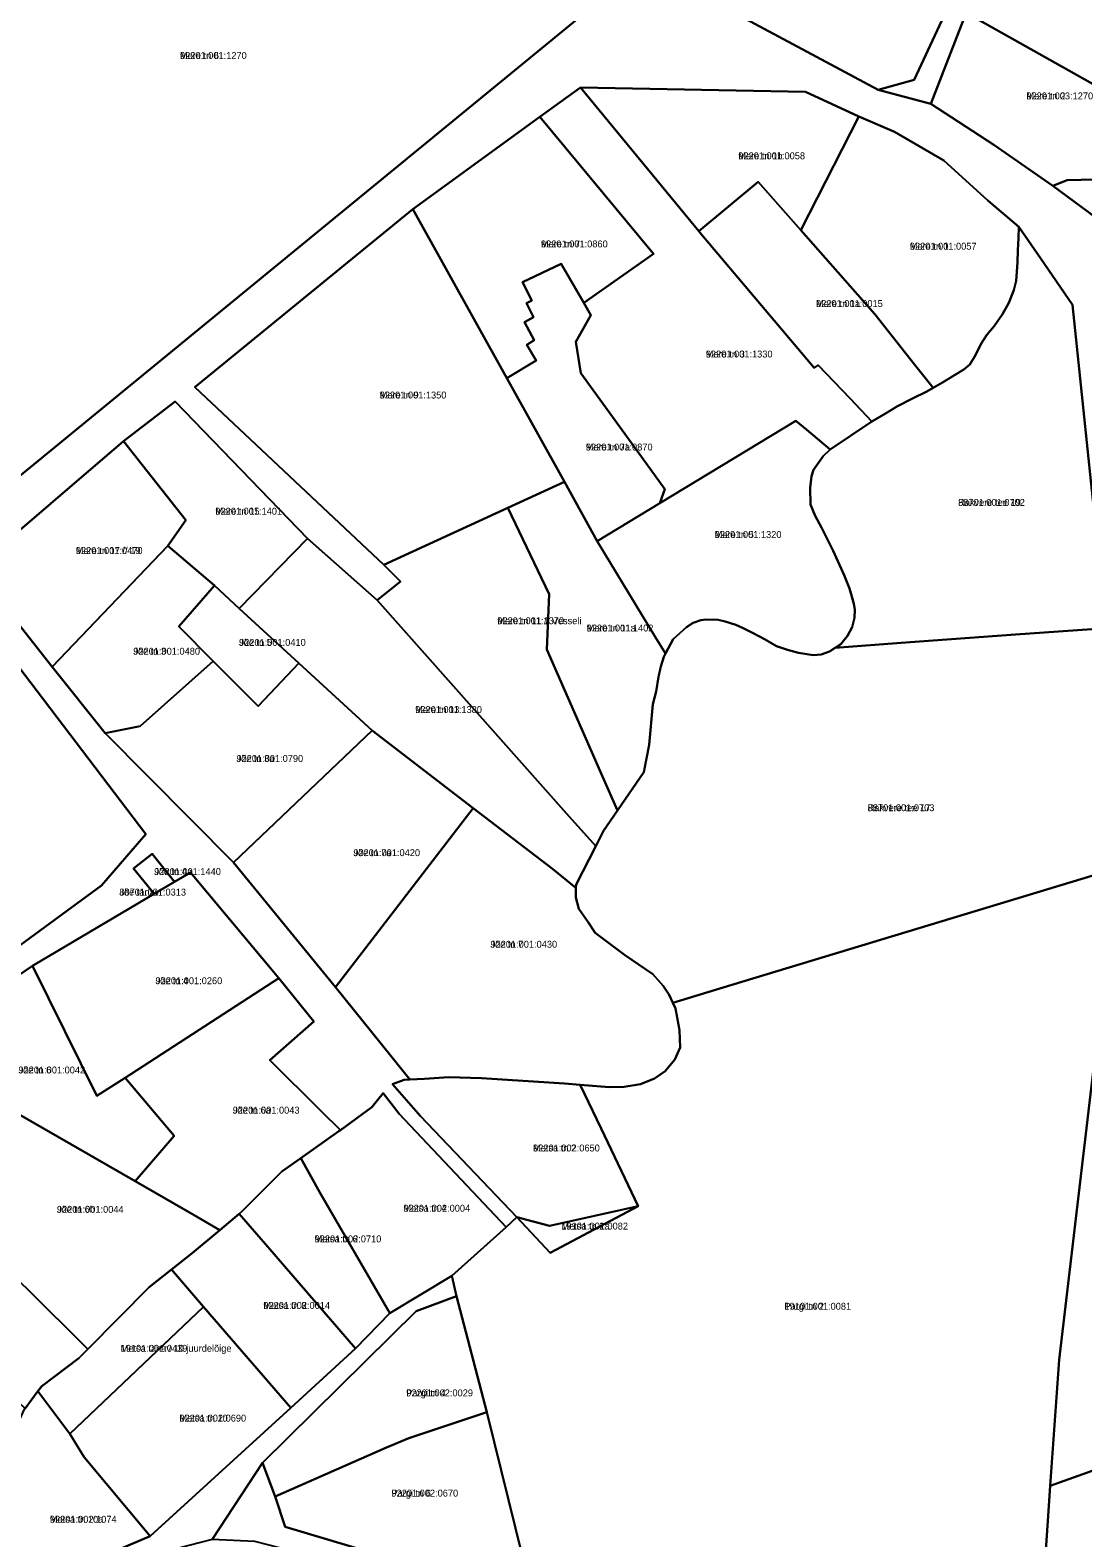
# Model space of a CAD drawing. Extents: x 601493 to 643081, y 6584980 to 6634019.
# Drawn here: x 611108.4 to 611337.1, y 6605926.7 to 6606254.3 of the extents above; entities that cross this region are included whole.
import ezdxf

# ---------------------------------------------------------------- set-up
doc = ezdxf.new("R2010")
doc.units = 0
for name, color, linetype in [('L_AADRESS', 7, 'Continuous'), ('PIIR', 7, 'Continuous'), ('TUNNUS', 7, 'Continuous')]:
    doc.layers.add(name, color=color, linetype=linetype)

msp = doc.modelspace()

# ---------------------------------------------------------------- linework, layer by layer
at = {"layer": 'PIIR'}
for points in [[(611073.07, 6606159.9), (611078.99, 6606164.44), (611082.73, 6606167.29), (611091.42, 6606169.43), (611091.64, 6606206.61), (611091.81, 6606222.53), (611073.07, 6606249.53), (611051.85, 6606278.36), (611112.41, 6606311.99), (611135.51, 6606313.25), (611230.04, 6606258.95), (611087.53, 6606142.22)], [(611277.56, 6606296.99), (611315.97, 6606276.84), (611300.48, 6606243.53), (611292.64, 6606241.37), (611262.74, 6606257.35)], [(611324.56, 6606288.83), (611368.17, 6606266), (611376.6, 6606261.93), (611373.27, 6606256.12), (611370.12, 6606250.96), (611367.92, 6606249.23), (611366.42, 6606245.46), (611365.91, 6606242.46), (611365.34, 6606235.12), (611363.34, 6606229.38), (611363.2, 6606229.23), (611353.45, 6606234.67), (611311.77, 6606258.08)], [(611311.77, 6606258.08), (611353.45, 6606234.67), (611363.2, 6606229.23), (611359.36, 6606225.29), (611354.7, 6606223.04), (611348.74, 6606221.93), (611342.84, 6606221.9), (611333.76, 6606221.74), (611330.64, 6606220.47), (611317.77, 6606229.4), (611304.12, 6606238.32)], [(611370.4, 6606236.93), (611381.02, 6606223.83), (611344.14, 6606210.31), (611341.44, 6606212.51), (611330.64, 6606220.47), (611333.76, 6606221.74), (611342.84, 6606221.9), (611348.74, 6606221.93), (611354.7, 6606223.04), (611359.36, 6606225.29), (611363.2, 6606229.23), (611363.34, 6606229.38), (611365.34, 6606235.12), (611365.91, 6606242.46)], [(611246.29, 6606154.58), (611241.26, 6606161.62), (611228.07, 6606179.75), (611226.98, 6606186.56), (611230.24, 6606192.36), (611228.7, 6606195.05), (611243.82, 6606205.7), (611219.12, 6606235.49), (611227.99, 6606241.87), (611253.69, 6606210.63), (611254.28, 6606209.89), (611278.76, 6606180.94), (611279.59, 6606181.5), (611286.54, 6606174.26), (611291.31, 6606169.28), (611282.23, 6606163.19), (611277.14, 6606167.43), (611274.76, 6606169.42), (611245.24, 6606151.52)], [(611253.69, 6606210.63), (611227.99, 6606241.87), (611276.84, 6606240.94), (611288.44, 6606235.52), (611275.82, 6606210.84), (611266.56, 6606221.33)], [(611228.7, 6606195.05), (611223.78, 6606203.52), (611215.38, 6606199.56), (611217.43, 6606195.57), (611216.23, 6606194.96), (611217.79, 6606191.95), (611215.83, 6606190.86), (611217.94, 6606186.97), (611216.34, 6606185.94), (611218.35, 6606182.51), (611211.99, 6606178.72), (611191.51, 6606215.38), (611219.12, 6606235.49), (611243.82, 6606205.7)], [(611300.56, 6606181.68), (611291.95, 6606192.59), (611275.82, 6606210.84), (611288.44, 6606235.52), (611296.2, 6606232.19), (611306.95, 6606225.97), (611316.5, 6606217.31), (611323.26, 6606211.58), (611323.17, 6606209.11), (611323, 6606206.51), (611322.91, 6606203.79), (611322.64, 6606199.87), (611322.13, 6606197.82), (611321.05, 6606195.06), (611319.71, 6606192.62), (611317.87, 6606190), (611316.29, 6606188.07), (611315, 6606186.07), (611313.84, 6606183.7), (611312.59, 6606181.67), (611311.28, 6606180.59), (611309.28, 6606179.34), (611306.62, 6606177.78), (611304.63, 6606176.6)], [(611286.54, 6606174.26), (611279.59, 6606181.5), (611278.76, 6606180.94), (611254.28, 6606209.89), (611253.69, 6606210.63), (611266.56, 6606221.33), (611275.82, 6606210.84), (611291.95, 6606192.59), (611300.56, 6606181.68), (611304.63, 6606176.6), (611303.25, 6606175.77), (611300.1, 6606174.26), (611296.84, 6606172.57), (611294.24, 6606171.04), (611291.31, 6606169.28)], [(611144.2, 6606176.72), (611191.51, 6606215.38), (611211.99, 6606178.72), (611224.47, 6606156.13), (611212.22, 6606150.48), (611185.27, 6606138.15)], [(611323.26, 6606211.58), (611327.92, 6606204.73), (611334.85, 6606194.62), (611342.19, 6606124.36), (611322.52, 6606122.99), (611297.62, 6606121.14), (611283.3, 6606120.09), (611284.54, 6606120.89), (611285.99, 6606122.69), (611287, 6606124.59), (611287.51, 6606126.64), (611287.56, 6606128.43), (611287.4, 6606129.67), (611286.46, 6606133.01), (611285.26, 6606135.86), (611282.91, 6606141.14), (611281.87, 6606143.17), (611280.36, 6606146.26), (611278.97, 6606148.77), (611277.98, 6606151.2), (611277.89, 6606154.89), (611278.15, 6606157.41), (611278.64, 6606158.8), (611280.74, 6606161.76), (611282.23, 6606163.19), (611291.31, 6606169.28), (611294.24, 6606171.04), (611296.84, 6606172.57), (611300.1, 6606174.26), (611303.25, 6606175.77), (611304.63, 6606176.6), (611306.62, 6606177.78), (611309.28, 6606179.34), (611311.28, 6606180.59), (611312.59, 6606181.67), (611313.84, 6606183.7), (611315, 6606186.07), (611316.29, 6606188.07), (611317.87, 6606190), (611319.71, 6606192.62), (611321.05, 6606195.06), (611322.13, 6606197.82), (611322.64, 6606199.87), (611322.91, 6606203.79), (611323, 6606206.51), (611323.17, 6606209.11)], [(611211.99, 6606178.72), (611218.35, 6606182.51), (611216.34, 6606185.94), (611217.94, 6606186.97), (611215.83, 6606190.86), (611217.79, 6606191.95), (611216.23, 6606194.96), (611217.43, 6606195.57), (611215.38, 6606199.56), (611223.78, 6606203.52), (611228.7, 6606195.05), (611230.24, 6606192.36), (611226.98, 6606186.56), (611228.07, 6606179.75), (611241.26, 6606161.62), (611246.29, 6606154.58), (611245.24, 6606151.52), (611231.59, 6606143.23), (611224.47, 6606156.13)], [(611138.3, 6606142.23), (611142.23, 6606147.83), (611128.64, 6606165.01), (611139.88, 6606173.65), (611168.62, 6606143.88), (611153.84, 6606128.66), (611148.43, 6606133.64)], [(611261.7, 6606125.05), (611259.4, 6606125.8), (611257.91, 6606126.15), (611255.2, 6606126.24), (611254.12, 6606126.07), (611252.46, 6606125.49), (611251.01, 6606124.58), (611249.56, 6606123.26), (611248.12, 6606121.94), (611246.43, 6606118.83), (611244.21, 6606122.49), (611231.59, 6606143.23), (611245.24, 6606151.52), (611274.76, 6606169.42), (611277.14, 6606167.43), (611282.23, 6606163.19), (611280.74, 6606161.76), (611278.64, 6606158.8), (611278.15, 6606157.41), (611277.89, 6606154.89), (611277.98, 6606151.2), (611278.97, 6606148.77), (611280.36, 6606146.26), (611281.87, 6606143.17), (611282.91, 6606141.14), (611285.26, 6606135.86), (611286.46, 6606133.01), (611287.11, 6606130.75), (611287.4, 6606129.67), (611287.56, 6606128.43), (611287.51, 6606126.64), (611287, 6606124.59), (611285.99, 6606122.69), (611284.54, 6606120.89), (611283.3, 6606120.09), (611282.07, 6606119.29), (611280.29, 6606118.65), (611278.52, 6606118.49), (611275.34, 6606118.98), (611272.96, 6606119.64), (611270.55, 6606120.42), (611268.09, 6606121.87), (611265.38, 6606123.32), (611263.33, 6606124.37)], [(611098.2, 6606134.91), (611097.49, 6606138.32), (611128.64, 6606165.01), (611142.23, 6606147.83), (611138.3, 6606142.23), (611113.17, 6606115.93)], [(611232.77, 6606092.12), (611220.63, 6606119.72), (611221.14, 6606131.75), (611212.22, 6606150.48), (611224.47, 6606156.13), (611231.59, 6606143.23), (611244.21, 6606122.49), (611246.43, 6606118.83), (611246.07, 6606118.1), (611245.46, 6606116.05), (611244.94, 6606113.77), (611244.39, 6606110.61), (611243.72, 6606107.85), (611242.89, 6606099.03), (611241.72, 6606093.04), (611236.02, 6606084.73)], [(611188.83, 6606134.52), (611185.27, 6606138.15), (611212.22, 6606150.48), (611221.14, 6606131.75), (611220.63, 6606119.72), (611232.77, 6606092.12), (611236.02, 6606084.73), (611233.01, 6606080.34), (611231.31, 6606077.02), (611225.51, 6606083.47), (611183.77, 6606130.41)], [(611166.77, 6606116.75), (611153.84, 6606128.66), (611168.62, 6606143.88), (611183.77, 6606130.41), (611225.51, 6606083.47), (611231.31, 6606077.02), (611227.01, 6606068.68), (611226.99, 6606067.97), (611221.89, 6606072.03), (611204.68, 6606085.23), (611182.7, 6606102.14)], [(611124.71, 6606101.57), (611113.17, 6606115.93), (611138.3, 6606142.23), (611148.43, 6606133.64), (611140.7, 6606124.71), (611148.19, 6606117.17), (611132.26, 6606103.1)], [(611089.51, 6606133.5), (611093.31, 6606132.38), (611133.53, 6606079.59), (611123.86, 6606068.45), (611083.02, 6606038.54), (611079.4, 6606042.41), (611056.85, 6606072.14), (611038.62, 6606094.13)], [(611153.84, 6606128.66), (611166.77, 6606116.75), (611157.95, 6606107.4), (611148.19, 6606117.17), (611140.7, 6606124.71), (611148.43, 6606133.64)], [(611124.71, 6606101.57), (611132.26, 6606103.1), (611148.19, 6606117.17), (611157.95, 6606107.4), (611166.77, 6606116.75), (611182.7, 6606102.14), (611152.54, 6606073.41)], [(611182.7, 6606102.14), (611204.68, 6606085.23), (611174.75, 6606046.38), (611152.54, 6606073.41)], [(611246.39, 6606028.12), (611244.08, 6606026.53), (611240.98, 6606025.3), (611237.5, 6606024.71), (611234.18, 6606024.6), (611227.92, 6606025.14), (611224.51, 6606025.44), (611206.43, 6606026.57), (611199.34, 6606026.78), (611194.09, 6606026.42), (611190.88, 6606026.29), (611186.78, 6606031.41), (611174.75, 6606046.38), (611204.68, 6606085.23), (611221.89, 6606072.03), (611226.99, 6606067.97), (611226.96, 6606065.83), (611227.59, 6606063.35), (611229.61, 6606060.45), (611231.17, 6606058.18), (611237.54, 6606053.35), (611243.7, 6606049.16), (611245.96, 6606046.66), (611247.24, 6606044.7), (611248.07, 6606042.95), (611248.65, 6606041.72), (611249.51, 6606036.99), (611249.65, 6606033.22), (611248.51, 6606030.6)], [(611130.88, 6606072.16), (611134.88, 6606075.34), (611139.77, 6606069.22), (611135.33, 6606066.63)], [(611135.33, 6606066.63), (611139.77, 6606069.22), (611143.26, 6606071.26), (611162.39, 6606048.3), (611129, 6606026.64), (611122.9, 6606022.74), (611108.88, 6606051.01)], [(611086.3, 6606035.65), (611108.88, 6606051.01), (611122.9, 6606022.74), (611129, 6606026.64), (611139.71, 6606014.03), (611131.2, 6606004.19), (611091.61, 6606026.92)], [(611149.59, 6605993.54), (611144.02, 6605996.77), (611131.2, 6606004.19), (611139.71, 6606014.03), (611129, 6606026.64), (611162.39, 6606048.3), (611170.01, 6606038.89), (611160.46, 6606030.48), (611171.66, 6606019.43), (611175.84, 6606015.31), (611175.45, 6606015.04), (611167.2, 6606009.18), (611163.1, 6606006.26), (611154.49, 6605997.64), (611153.83, 6605997.09)], [(611039.61, 6606017.31), (611054.32, 6606028.38), (611056.76, 6606025.9), (611072.83, 6606007.94), (611094.39, 6605989.62), (611096.54, 6605991.79), (611117.79, 6605970.79), (611120.89, 6605967.72), (611118.94, 6605965.75), (611110.9, 6605959.65), (611110.08, 6605958.56), (611107.28, 6605954.8), (611103.8, 6605958.04), (611079.61, 6605980.43), (611073.09, 6605983.62)], [(611117.79, 6605970.79), (611096.54, 6605991.79), (611094.39, 6605989.62), (611072.83, 6606007.94), (611091.61, 6606026.92), (611131.2, 6606004.19), (611144.02, 6605996.77), (611149.59, 6605993.54), (611143.6, 6605988.55), (611139.07, 6605984.99), (611134.22, 6605981.16), (611120.89, 6605967.72)], [(611193.18, 6606018.33), (611187.16, 6606025.26), (611189.65, 6606026.23), (611190.88, 6606026.29), (611194.09, 6606026.42), (611199.34, 6606026.78), (611206.43, 6606026.57), (611224.51, 6606025.44), (611227.92, 6606025.14), (611232.45, 6606015.64), (611240.51, 6605998.74), (611221.23, 6605994.51), (611214.14, 6605996.36)], [(611211.8, 6605994.17), (611199.99, 6605983.63), (611186.58, 6605975.54), (611171.31, 6606001.71), (611167.2, 6606009.18), (611175.45, 6606015.04), (611175.84, 6606015.31), (611182.6, 6606020.25), (611185.07, 6606023.35), (611188.55, 6606018.82)], [(611153.83, 6605997.09), (611154.49, 6605997.64), (611163.1, 6606006.26), (611167.2, 6606009.18), (611171.31, 6606001.71), (611186.58, 6605975.54), (611179.05, 6605967.82), (611160.01, 6605989.92)], [(611153.83, 6605997.09), (611160.01, 6605989.92), (611179.05, 6605967.82), (611165.05, 6605954.92), (611146.08, 6605976.87), (611139.07, 6605984.99), (611143.6, 6605988.55), (611149.59, 6605993.54)], [(611221.39, 6605988.63), (611214.14, 6605996.36), (611221.23, 6605994.51), (611240.51, 6605998.74)], [(611398.2, 6605988.02), (611398.78, 6605987.53), (611378.18, 6605962.48), (611362.28, 6605937.88), (611344.47, 6605900.82), (611328.28, 6605846.84), (611323.81, 6605825.14), (611317.63, 6605878.14), (611320.38, 6605884.78), (611326.67, 6605888.22), (611330.06, 6605937.96), (611339.17, 6605941.28), (611353.74, 6605933.06)], [(611009.76, 6605850.83), (611062.06, 6605884.88), (611062.56, 6605888.3), (611027.99, 6605894.63), (611011.92, 6605894.26), (611012.29, 6605899.01), (611022.49, 6605900.98), (611051.97, 6605895.45), (611070.25, 6605889.12), (611088.7, 6605901.38), (611123.51, 6605922.45), (611134.49, 6605927.03), (611165.05, 6605954.92), (611179.05, 6605967.82), (611186.58, 6605975.54), (611199.99, 6605983.63), (611201.01, 6605979.17), (611192.29, 6605975.95), (611158.84, 6605942.95), (611147.96, 6605926.34), (611137.5, 6605923.67), (611115.81, 6605912.81), (611082.29, 6605891.66), (611013.55, 6605849.98)], [(611120.89, 6605967.72), (611134.22, 6605981.16), (611139.07, 6605984.99), (611146.08, 6605976.87), (611117.01, 6605949.26), (611110.08, 6605958.56), (611110.9, 6605959.65), (611118.94, 6605965.75)], [(611134.49, 6605927.03), (611120.11, 6605944.23), (611117.01, 6605949.26), (611146.08, 6605976.87), (611165.05, 6605954.92)], [(611158.84, 6605942.95), (611192.29, 6605975.95), (611201.01, 6605979.17), (611207.62, 6605953.98), (611190.69, 6605948.32), (611185.83, 6605946.35), (611161.61, 6605935.68)], [(611110.08, 6605958.56), (611117.01, 6605949.26), (611120.11, 6605944.23), (611134.49, 6605927.03), (611123.51, 6605922.45), (611088.7, 6605901.38), (611081.69, 6605912.32), (611074.1, 6605924.42), (611080.7, 6605923.59), (611085.81, 6605925.29), (611092.15, 6605928.73), (611097.93, 6605934.81), (611102.16, 6605942.64), (611105.98, 6605952.13), (611107.25, 6605954.76), (611107.28, 6605954.8)], [(611207.62, 6605953.98), (611215.46, 6605922.32), (611208.71, 6605917.32), (611201.16, 6605917.95), (611163.79, 6605929.05), (611161.61, 6605935.68), (611185.83, 6605946.35), (611190.69, 6605948.32)], [(611147.96, 6605926.34), (611158.84, 6605942.95), (611161.61, 6605935.68), (611163.79, 6605929.05), (611201.16, 6605917.95), (611208.71, 6605917.32), (611215.46, 6605922.32), (611237.35, 6605920.93), (611276.69, 6605899.86), (611320.38, 6605884.78), (611317.63, 6605878.14), (611300, 6605886.11), (611286.78, 6605891.22), (611247.61, 6605907.64), (611225.45, 6605916.03), (611218.77, 6605915.13), (611210.66, 6605912.84), (611207.12, 6605912.54), (611197.19, 6605914.12), (611165.66, 6605923.69), (611157.22, 6605925.86)]]:
    msp.add_lwpolyline(points, close=True, dxfattribs=at)
for points in [[(611311.77, 6606258.08), (611304.12, 6606238.32), (611292.64, 6606241.37), (611300.48, 6606243.53), (611315.97, 6606276.84)], [(611087.53, 6606142.22), (611230.04, 6606258.95)], [(611262.74, 6606257.35), (611292.64, 6606241.37), (611304.12, 6606238.32), (611317.77, 6606229.4), (611330.64, 6606220.47), (611341.44, 6606212.51)], [(611342.19, 6606124.36), (611334.85, 6606194.62), (611327.92, 6606204.73), (611323.26, 6606211.58), (611316.5, 6606217.31), (611306.95, 6606225.97), (611296.2, 6606232.19), (611288.44, 6606235.52), (611276.84, 6606240.94), (611227.99, 6606241.87), (611219.12, 6606235.49), (611191.51, 6606215.38), (611144.2, 6606176.72), (611185.27, 6606138.15), (611188.83, 6606134.52), (611183.77, 6606130.41), (611168.62, 6606143.88), (611139.88, 6606173.65), (611128.64, 6606165.01), (611097.49, 6606138.32)], [(611098.2, 6606134.91), (611113.17, 6606115.93), (611124.71, 6606101.57), (611152.54, 6606073.41), (611174.75, 6606046.38), (611186.78, 6606031.41), (611190.88, 6606026.29), (611189.65, 6606026.23), (611187.16, 6606025.26), (611193.18, 6606018.33), (611214.14, 6605996.36), (611211.8, 6605994.17), (611188.55, 6606018.82), (611185.07, 6606023.35), (611182.6, 6606020.25), (611175.84, 6606015.31), (611171.66, 6606019.43), (611160.46, 6606030.48), (611170.01, 6606038.89), (611162.39, 6606048.3), (611143.26, 6606071.26), (611139.77, 6606069.22), (611134.88, 6606075.34), (611130.88, 6606072.16), (611135.33, 6606066.63), (611108.88, 6606051.01), (611086.3, 6606035.65)], [(611083.02, 6606038.54), (611123.86, 6606068.45), (611133.53, 6606079.59), (611093.31, 6606132.38)], [(611344.57, 6606072.24), (611260.61, 6606046.76), (611248.07, 6606042.95), (611247.24, 6606044.7), (611245.96, 6606046.66), (611243.7, 6606049.16), (611237.54, 6606053.35), (611231.17, 6606058.18), (611229.61, 6606060.45), (611227.59, 6606063.35), (611226.96, 6606065.83), (611226.99, 6606067.97), (611227.01, 6606068.68), (611231.31, 6606077.02), (611233.01, 6606080.34), (611236.02, 6606084.73), (611241.72, 6606093.04), (611242.89, 6606099.03), (611243.72, 6606107.85), (611244.39, 6606110.61), (611244.94, 6606113.77), (611245.46, 6606116.05), (611246.07, 6606118.1), (611246.43, 6606118.83), (611248.12, 6606121.94), (611249.56, 6606123.26), (611251.01, 6606124.58), (611252.46, 6606125.49), (611254.12, 6606126.07), (611255.2, 6606126.24), (611257.91, 6606126.15), (611259.4, 6606125.8), (611261.7, 6606125.05), (611263.33, 6606124.37), (611265.38, 6606123.32), (611268.09, 6606121.87), (611270.55, 6606120.42), (611272.96, 6606119.64), (611275.34, 6606118.98), (611278.52, 6606118.49), (611280.29, 6606118.65), (611282.07, 6606119.29), (611283.3, 6606120.09), (611297.62, 6606121.14), (611322.52, 6606122.99), (611342.19, 6606124.36)], [(611215.46, 6605922.32), (611207.62, 6605953.98), (611201.01, 6605979.17), (611199.99, 6605983.63), (611211.8, 6605994.17), (611214.14, 6605996.36), (611221.39, 6605988.63), (611240.51, 6605998.74), (611232.45, 6606015.64), (611227.92, 6606025.14), (611234.18, 6606024.6), (611237.5, 6606024.71), (611240.98, 6606025.3), (611244.08, 6606026.53), (611246.39, 6606028.12), (611248.51, 6606030.6), (611249.65, 6606033.22), (611249.51, 6606036.99), (611248.65, 6606041.72), (611248.07, 6606042.95), (611260.61, 6606046.76), (611344.57, 6606072.24), (611331.97, 6605965.39), (611330.06, 6605937.96), (611326.67, 6605888.22)], [(611339.17, 6605941.28), (611330.06, 6605937.96), (611331.97, 6605965.39), (611344.57, 6606072.24)]]:
    msp.add_lwpolyline(points, dxfattribs=at)

# ---------------------------------------------------------------- texts
at = {"layer": 'L_AADRESS'}
for s, p in [('Mere tn 6', (611140.95, 6606248.05)), ('Mere tn 2', (611324.87, 6606239.27)), ('Mere tn 1b', (611262.27, 6606226.25)), ('Mere tn 7', (611219.39, 6606207.1)), ('Mere tn 1', (611299.54, 6606206.61)), ('Mere tn 1a', (611279.16, 6606194.14)), ('Mere tn 3', (611255.21, 6606183.18)), ('Mere tn 9', (611184.34, 6606174.27)), ('Mere tn 7a', (611229.14, 6606162.97)), ('Mere tn 15', (611148.63, 6606149.02)), ('Rakvere tee 19', (611310.04, 6606150.94)), ('Mere tn 5', (611257.14, 6606143.96)), ('Mere tn 17 // 19', (611118.31, 6606140.47)), ('Mere tn 11 // Vesseli', (611209.9, 6606125.22)), ('Mere tn 11a', (611229.32, 6606123.64)), ('Jõe tn 5', (611153.77, 6606120.52)), ('Jõe tn 3', (611130.8, 6606118.59)), ('Mere tn 13', (611192.06, 6606105.92)), ('Jõe tn 3a', (611153.21, 6606095.29)), ('Rakvere tee 17', (611290.37, 6606084.59)), ('Jõe tn 7a', (611178.61, 6606074.82)), ('Jõe tn 4a', (611135.33, 6606070.71)), ('Jõe tänav', (611127.76, 6606066.25)), ('Jõe tn 7', (611208.4, 6606054.92)), ('Jõe tn 4', (611135.63, 6606047)), ('Jõe tn 6', (611105.84, 6606027.6)), ('Jõe tn 6a', (611152.42, 6606018.87)), ('Metsa tn 2', (611217.67, 6606010.65)), ('Jõe tn 6b', (611114.2, 6605997.32)), ('Metsa tn 4', (611189.5, 6605997.56)), ('Metsa tn 2a', (611223.8, 6605993.68)), ('Metsa tn 6', (611170.2, 6605990.9)), ('Metsa tn 8', (611159.06, 6605976.44)), ('Pargi tn 2', (611272.28, 6605976.26)), ('Metsa tänav 10 juurdelõige', (611128.06, 6605967.12)), ('Pargi tn 4', (611190.11, 6605957.43)), ('Metsa tn 10', (611140.82, 6605951.95)), ('Pargi tn 6', (611186.89, 6605935.65)), ('Metsa tn 10a', (611112.68, 6605929.97))]:
    msp.add_text(s, height=1.5, dxfattribs=at).set_placement(p)
at = {"layer": 'TUNNUS'}
for s, p in [('92201:001:1270', (611140.95, 6606248.05)), ('92201:003:1270', (611324.87, 6606239.27)), ('92201:001:0058', (611262.27, 6606226.25)), ('92201:001:0860', (611219.39, 6606207.1)), ('92201:001:0057', (611299.54, 6606206.61)), ('92201:001:0015', (611279.16, 6606194.14)), ('92201:001:1330', (611255.21, 6606183.18)), ('92201:001:1350', (611184.34, 6606174.27)), ('92201:001:0870', (611229.14, 6606162.97)), ('92201:001:1401', (611148.63, 6606149.02)), ('88701:001:0702', (611310.04, 6606150.94)), ('92201:001:1320', (611257.14, 6606143.96)), ('92201:001:0470', (611118.31, 6606140.47)), ('92201:001:1370', (611209.9, 6606125.22)), ('92201:001:1402', (611229.32, 6606123.64)), ('92201:001:0410', (611153.77, 6606120.52)), ('92201:001:0480', (611130.8, 6606118.59)), ('92201:001:1380', (611192.06, 6606105.92)), ('92201:001:0790', (611153.21, 6606095.29)), ('88701:001:0703', (611290.37, 6606084.59)), ('92201:001:0420', (611178.61, 6606074.82)), ('92201:001:1440', (611135.33, 6606070.71)), ('88701:001:0313', (611127.76, 6606066.25)), ('92201:001:0430', (611208.4, 6606054.92)), ('92201:001:0260', (611135.63, 6606047)), ('92201:001:0042', (611105.84, 6606027.6)), ('92201:001:0043', (611152.42, 6606018.87)), ('92201:002:0650', (611217.67, 6606010.65)), ('92201:001:0044', (611114.2, 6605997.32)), ('92201:002:0004', (611189.5, 6605997.56)), ('19101:001:0082', (611223.8, 6605993.68)), ('92201:002:0710', (611170.2, 6605990.9)), ('92201:002:0014', (611159.06, 6605976.44)), ('19101:001:0081', (611272.28, 6605976.26)), ('19101:001:0439', (611128.06, 6605967.12)), ('92201:002:0029', (611190.11, 6605957.43)), ('92201:002:0690', (611140.82, 6605951.95)), ('92201:002:0670', (611186.89, 6605935.65)), ('92201:002:1074', (611112.68, 6605929.97))]:
    msp.add_text(s, height=1.5, dxfattribs=at).set_placement(p)

doc.saveas('drawing.dxf')
